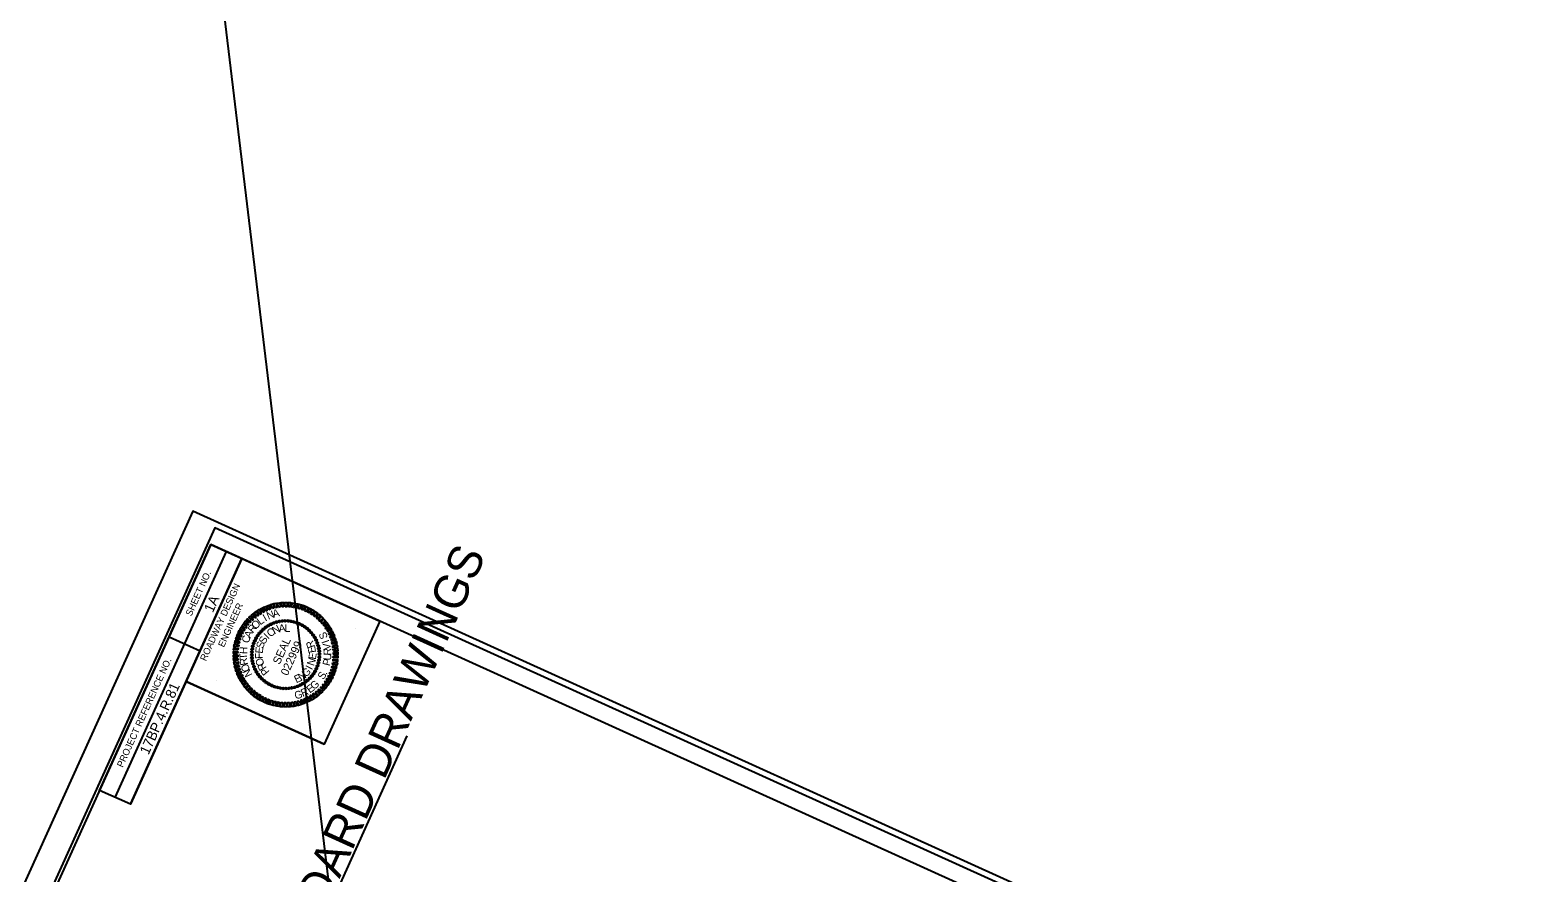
# Model space of a CAD drawing. Extents: x 1744741 to 2014229, y 466994 to 951338.
# Drawn here: x 2007510 to 2010026, y 478827 to 480232 of the extents above; entities that cross this region are included whole.
import ezdxf

# ---------------------------------------------------------------- set-up
doc = ezdxf.new("R2010")
doc.units = 0
for name, color, linetype in [('Old_Level_1', 7, 'Continuous'), ('Prop Guardrail', 7, 'Continuous'), ('Prop Guardrail Anchor Unit CELL', 7, 'Continuous'), ('Sheet Data Field CELL', 7, 'Continuous'), ('Sheet Plan CELL', 7, 'Continuous'), ('Sheet Plot Border Inside CELL', 7, 'Continuous'), ('Sheet Plot Border Outside CELL', 7, 'Continuous'), ('Sheet Sticker Preliminary CELL', 7, 'Continuous')]:
    doc.layers.add(name, color=color, linetype=linetype)

msp = doc.modelspace()

# ---------------------------------------------------------------- linework, layer by layer
at = {"layer": 'Old_Level_1'}
msp.add_line((2007533.4, 477718), (2008139.4, 479055), dxfattribs=at)
at = {"layer": 'Prop Guardrail'}
for p, q in [((2007903.6, 479236.4), (2007903.6, 479236.4)), ((2007907.8, 479239.1), (2007907.8, 479239.1)), ((2007912.1, 479241.4), (2007912.1, 479241.4)), ((2007916.7, 479243.3), (2007916.7, 479243.3)), ((2007921.3, 479244.9), (2007921.3, 479244.9)), ((2007926, 479246), (2007926, 479246)), ((2007931, 479246.7), (2007931, 479246.7)), ((2007935.9, 479247), (2007935.9, 479247)), ((2007940.7, 479246.9), (2007940.7, 479246.9)), ((2007945.7, 479246.2), (2007945.7, 479246.2)), ((2007950.6, 479245.1), (2007950.6, 479245.1)), ((2007955.2, 479243.8), (2007955.2, 479243.8)), ((2007959.8, 479241.9), (2007959.8, 479241.9)), ((2007964.2, 479239.7), (2007964.2, 479239.7)), ((2007968.4, 479237), (2007968.4, 479237)), ((2007885, 479213.8), (2007885, 479213.8)), ((2007887.3, 479218.2), (2007887.3, 479218.2)), ((2007889.9, 479222.4), (2007889.9, 479222.4)), ((2007892.9, 479226.3), (2007892.9, 479226.3)), ((2007896.1, 479230.1), (2007896.1, 479230.1)), ((2007899.8, 479233.3), (2007899.8, 479233.3)), ((2007972.3, 479234.2), (2007972.3, 479234.2)), ((2007976, 479230.9), (2007976, 479230.9)), ((2007979.3, 479227.3), (2007979.3, 479227.3)), ((2007982.5, 479223.4), (2007982.5, 479223.4)), ((2007985.1, 479219.2), (2007985.1, 479219.2)), ((2007987.5, 479214.9), (2007987.5, 479214.9)), ((2007989.4, 479210.4), (2007989.4, 479210.4)), ((2008052.6, 479233.7), (2008052.6, 479233.7)), ((2007880.1, 479194.8), (2007880.1, 479194.8)), ((2007880.1, 479189.9), (2007880.1, 479189.9)), ((2007880.8, 479199.7), (2007880.8, 479199.7)), ((2007881.8, 479204.5), (2007881.8, 479204.5)), ((2007883.2, 479209.2), (2007883.2, 479209.2)), ((2007936.5, 479190.5), (2007936.5, 479190.5)), ((2007991, 479205.7), (2007991, 479205.7)), ((2007992, 479200.9), (2007992, 479200.9)), ((2007992.8, 479196), (2007992.8, 479196)), ((2007992.8, 479186.2), (2007992.8, 479186.2)), ((2007993, 479191.1), (2007993, 479191.1)), ((2007880.3, 479184.9), (2007880.3, 479184.9)), ((2007881.1, 479180), (2007881.1, 479180)), ((2007882.1, 479175.2), (2007882.1, 479175.2)), ((2007883.7, 479170.6), (2007883.7, 479170.6)), ((2007885.6, 479166), (2007885.6, 479166)), ((2007887.9, 479161.8), (2007887.9, 479161.8)), ((2007985.6, 479162.8), (2007985.6, 479162.8)), ((2007987.9, 479167.2), (2007987.9, 479167.2)), ((2007989.7, 479171.8), (2007989.7, 479171.8)), ((2007991.1, 479176.5), (2007991.1, 479176.5)), ((2007992.3, 479181.3), (2007992.3, 479181.3)), ((2007820.5, 479147.2), (2007820.5, 479147.2)), ((2007890.6, 479157.5), (2007890.6, 479157.5)), ((2007893.6, 479153.7), (2007893.6, 479153.7)), ((2007896.9, 479150.1), (2007896.9, 479150.1)), ((2007900.6, 479146.9), (2007900.6, 479146.9)), ((2007904.7, 479143.9), (2007904.7, 479143.9)), ((2007908.7, 479141.3), (2007908.7, 479141.3)), ((2007913.1, 479139.1), (2007913.1, 479139.1)), ((2007917.7, 479137.2), (2007917.7, 479137.2)), ((2007922.5, 479135.8), (2007922.5, 479135.8)), ((2007927.2, 479134.8), (2007927.2, 479134.8)), ((2007946.9, 479135), (2007946.9, 479135)), ((2007951.8, 479136), (2007951.8, 479136)), ((2007956.4, 479137.6), (2007956.4, 479137.6)), ((2007961, 479139.5), (2007961, 479139.5)), ((2007965.3, 479141.9), (2007965.3, 479141.9)), ((2007969.5, 479144.5), (2007969.5, 479144.5)), ((2007973.3, 479147.6), (2007973.3, 479147.6)), ((2007976.8, 479151), (2007976.8, 479151)), ((2007980.2, 479154.6), (2007980.2, 479154.6)), ((2007983, 479158.7), (2007983, 479158.7)), ((2007932.2, 479134.2), (2007932.2, 479134.2)), ((2007937, 479134), (2007937, 479134)), ((2007942.1, 479134.2), (2007942.1, 479134.2))]:
    msp.add_line(p, q, dxfattribs=at)
for points in [[(2007889, 479254.8), (2007884.3, 479260.1), (2007887.3, 479262.5), (2007891.1, 479256.1)], [(2007893.5, 479257.6), (2007889.2, 479263.8), (2007892.4, 479265.6), (2007895.8, 479259.3)], [(2007898.3, 479260.6), (2007894.4, 479266.7), (2007897.7, 479268.6), (2007900.6, 479261.8)], [(2007903.4, 479263.1), (2007899.7, 479269.7), (2007903.3, 479271), (2007905.7, 479264.4)], [(2007908.5, 479265.2), (2007905.6, 479271.8), (2007909.2, 479273.1), (2007910.9, 479266.1)], [(2007913.9, 479267.2), (2007911.3, 479273.9), (2007915, 479275), (2007916.4, 479267.8)], [(2007919.2, 479268.6), (2007916.9, 479275.6), (2007920.9, 479276.1), (2007921.6, 479269)], [(2007924.5, 479269.4), (2007923.1, 479276.6), (2007926.9, 479277.2), (2007927.3, 479270)], [(2007930.3, 479270.1), (2007929.2, 479277.4), (2007932.9, 479277.5), (2007932.7, 479270.5)], [(2007935.6, 479270.3), (2007935.2, 479277.7), (2007938.9, 479277.7), (2007938.3, 479270.3)], [(2007941.2, 479270.1), (2007941.3, 479277.5), (2007944.9, 479277.3), (2007943.9, 479270.1)], [(2007946.9, 479269.7), (2007947.3, 479277.2), (2007951.2, 479276.4), (2007949.5, 479269.3)], [(2007952.4, 479268.7), (2007953.2, 479276), (2007957, 479275.2), (2007954.9, 479268.3)], [(2007957.7, 479267.4), (2007959.3, 479274.8), (2007963, 479273.6), (2007960.4, 479266.8)], [(2007963, 479265.9), (2007965, 479273.1), (2007968.6, 479271.7), (2007965.5, 479265)], [(2007968.2, 479263.8), (2007970.8, 479270.7), (2007974.3, 479269.1), (2007970.7, 479262.7)], [(2007973.3, 479261.5), (2007976.3, 479268.2), (2007979.7, 479266.4), (2007975.7, 479260.2)], [(2007978.1, 479258.9), (2007981.6, 479265.1), (2007984.9, 479263.1), (2007980.3, 479257.2)], [(2007983, 479255.6), (2007986.6, 479261.8), (2007989.7, 479259.5), (2007984.7, 479254)], [(2007866.8, 479229.7), (2007860.4, 479233), (2007862.3, 479236.2), (2007868.3, 479232)], [(2007869.8, 479234.3), (2007863.6, 479238.1), (2007865.6, 479241.3), (2007871.2, 479236.7)], [(2007873.2, 479239.1), (2007866.9, 479243), (2007869.3, 479246.2), (2007874.6, 479241)], [(2007876.7, 479243.4), (2007871, 479247.7), (2007873.2, 479250.5), (2007878.3, 479245.3)], [(2007880.4, 479247.3), (2007875.1, 479252.4), (2007877.7, 479254.8), (2007882.4, 479249.4)], [(2007884.6, 479251.1), (2007879.6, 479256.3), (2007882.4, 479258.8), (2007886.6, 479252.9)], [(2007987.4, 479252.2), (2007991.5, 479258.1), (2007994.5, 479255.9), (2007989.1, 479250.5)], [(2007991.6, 479248.5), (2007996.2, 479254.1), (2007998.9, 479251.4), (2007993.2, 479246.5)], [(2007995.3, 479244.5), (2008000.4, 479249.8), (2008003, 479246.9), (2007997.1, 479242.5)], [(2007999.1, 479240.4), (2008004.2, 479245.2), (2008006.8, 479242.2), (2008000.6, 479238.3)], [(2008002.5, 479235.9), (2008008, 479240.5), (2008010.2, 479237.1), (2008003.6, 479233.6)], [(2007858.7, 479209.2), (2007851.6, 479210.3), (2007852.7, 479213.9), (2007859.6, 479211.7)], [(2007860.3, 479214.4), (2007853.2, 479216.1), (2007854.3, 479219.7), (2007861, 479217)], [(2007862, 479219.8), (2007855.1, 479222.1), (2007856.7, 479225.4), (2007863.1, 479222.3)], [(2007864.3, 479224.7), (2007857.6, 479227.5), (2007859.1, 479230.9), (2007865.4, 479227.2)], [(2008005.2, 479231.1), (2008011.3, 479235.2), (2008013.3, 479231.9), (2008006.7, 479228.9)], [(2008007.8, 479226.4), (2008014.3, 479229.9), (2008016, 479226.5), (2008009.2, 479224)], [(2008010.3, 479221), (2008016.8, 479224.4), (2008018.1, 479220.8), (2008011.2, 479218.6)], [(2008012.5, 479216), (2008018.9, 479218.6), (2008020.2, 479215), (2008013, 479213.4)], [(2008013.7, 479210.6), (2008020.7, 479212.9), (2008021.7, 479209.1), (2008014.3, 479208)], [(2007856.5, 479192.4), (2007849.3, 479192.3), (2007849.4, 479195.9), (2007856.8, 479195.2)], [(2007856.7, 479186.9), (2007849.5, 479186.1), (2007849.5, 479189.9), (2007856.7, 479189.6)], [(2007856.9, 479198.2), (2007849.7, 479198.5), (2007850.3, 479202), (2007857.3, 479200.6)], [(2007857.7, 479203.7), (2007850.3, 479204.3), (2007851.1, 479208.2), (2007858.3, 479206.1)], [(2008015.2, 479205.2), (2008022.1, 479206.8), (2008023, 479203.2), (2008015.4, 479202.4)], [(2008015.9, 479199.6), (2008023, 479201.1), (2008023.4, 479197), (2008016.3, 479197.1)], [(2008016.6, 479188.5), (2008023.8, 479188.6), (2008023.7, 479185.1), (2008016.1, 479185.8)], [(2008016.4, 479194.1), (2008023.6, 479194.8), (2008023.6, 479191), (2008016.4, 479191.3)], [(2007857.2, 479181.3), (2007849.9, 479180), (2007849.7, 479183.9), (2007856.9, 479183.9)], [(2007857.9, 479175.7), (2007851, 479174.2), (2007850.1, 479177.8), (2007857.7, 479178.5)], [(2007859.2, 479170.4), (2007852.2, 479168.2), (2007851.4, 479171.9), (2007858.6, 479173)], [(2007860.6, 479165), (2007854, 479162.4), (2007852.7, 479166), (2007860.1, 479167.6)], [(2007862.8, 479159.9), (2007856.3, 479156.5), (2007855, 479160.1), (2007861.9, 479162.3)], [(2008010.9, 479161.2), (2008018, 479158.9), (2008016.4, 479155.5), (2008009.8, 479158.8)], [(2008012.8, 479166.5), (2008019.7, 479164.9), (2008018.8, 479161.2), (2008011.9, 479164)], [(2008014.2, 479171.8), (2008021.5, 479170.6), (2008020.4, 479167), (2008013.5, 479169.2)], [(2008015.2, 479177.3), (2008022.8, 479176.6), (2008021.8, 479172.8), (2008014.8, 479174.9)], [(2008016, 479182.9), (2008023.3, 479182.5), (2008022.8, 479178.9), (2008015.8, 479180.3)], [(2007865.1, 479154.7), (2007858.8, 479151), (2007857.1, 479154.5), (2007863.9, 479156.9)], [(2007867.7, 479149.9), (2007861.8, 479145.8), (2007859.6, 479149.1), (2007866.4, 479152)], [(2007870.6, 479145), (2007864.9, 479140.6), (2007862.9, 479143.8), (2007869.3, 479147.5)], [(2007873.8, 479140.6), (2007868.7, 479135.9), (2007866.3, 479138.7), (2007872.5, 479142.7)], [(2007877.6, 479136.5), (2007872.5, 479131.2), (2007870.1, 479134), (2007875.8, 479138.6)], [(2007996.4, 479137.5), (2008002.1, 479133.2), (2007999.7, 479130.5), (2007994.6, 479135.7)], [(2007999.9, 479141.9), (2008006, 479138), (2008003.8, 479134.8), (2007998.3, 479140)], [(2008003.3, 479146.6), (2008009.5, 479142.8), (2008007.5, 479139.6), (2008001.7, 479144.4)], [(2008006.1, 479151.3), (2008012.7, 479147.9), (2008010.6, 479144.8), (2008004.8, 479148.9)], [(2008008.6, 479156.3), (2008015.5, 479153.4), (2008014, 479150.1), (2008007.5, 479153.8)], [(2007881.5, 479132.4), (2007876.7, 479126.9), (2007874.2, 479129.5), (2007879.7, 479134.5)], [(2007885.7, 479128.8), (2007881.6, 479122.9), (2007878.4, 479125.2), (2007883.8, 479130.5)], [(2007890.1, 479125.3), (2007886.4, 479119.2), (2007883.2, 479121.5), (2007888.2, 479127)], [(2007894.9, 479122.2), (2007891.5, 479115.8), (2007888.2, 479117.8), (2007892.6, 479123.8)], [(2007899.6, 479119.5), (2007896.6, 479112.9), (2007893.2, 479114.6), (2007897.2, 479120.8)], [(2007904.7, 479117.2), (2007902.3, 479110.3), (2007898.8, 479111.8), (2007902.2, 479118.3)], [(2007909.9, 479115.1), (2007907.9, 479108), (2007904.4, 479109.3), (2007907.4, 479116)], [(2007915.2, 479113.6), (2007913.8, 479106.2), (2007910.1, 479107.3), (2007912.5, 479114.2)], [(2007920.5, 479112.4), (2007919.7, 479105), (2007915.9, 479105.8), (2007918.2, 479112.6)], [(2007926, 479111.4), (2007925.6, 479103.8), (2007922, 479104.6), (2007923.7, 479111.6)], [(2007931.7, 479110.9), (2007931.8, 479103.4), (2007928, 479103.7), (2007929.2, 479110.8)], [(2007937.3, 479110.7), (2007937.9, 479103.3), (2007934, 479103.3), (2007934.6, 479110.7)], [(2007942.8, 479110.8), (2007943.9, 479103.5), (2007940, 479103.5), (2007940.2, 479110.5)], [(2007948.4, 479111.6), (2007950, 479104.3), (2007946.1, 479103.8), (2007945.8, 479110.9)], [(2007953.9, 479112.3), (2007956, 479105.5), (2007952.2, 479104.8), (2007951.3, 479112)], [(2007959.2, 479113.7), (2007961.8, 479107), (2007958.2, 479105.9), (2007956.5, 479113.2)], [(2007964.6, 479115.8), (2007967.5, 479109.1), (2007963.9, 479107.8), (2007962.2, 479114.9)], [(2007969.7, 479117.9), (2007973.2, 479111.4), (2007969.6, 479110), (2007967.4, 479116.6)], [(2007974.6, 479120.5), (2007978.7, 479114.2), (2007975.2, 479112.4), (2007972.3, 479119.2)], [(2007979.6, 479123.3), (2007984, 479117.1), (2007980.7, 479115.4), (2007977.3, 479121.6)], [(2007984.1, 479126.2), (2007988.9, 479120.8), (2007985.6, 479118.5), (2007982, 479124.8)], [(2007988.5, 479129.9), (2007993.5, 479124.6), (2007990.7, 479122.1), (2007986.5, 479128.1)], [(2007992.5, 479133.7), (2007998, 479128.5), (2007995.4, 479126.1), (2007990.8, 479131.6)]]:
    msp.add_lwpolyline(points, close=True, dxfattribs=at)
for centre, major_axis in [((2007903.6, 479236.3), (-0.94, 1.32)), ((2007907.8, 479239), (-0.83, 1.39)), ((2007912.1, 479241.3), (-0.7, 1.46)), ((2007916.6, 479243.3), (-0.57, 1.52)), ((2007921.3, 479244.8), (-0.44, 1.56)), ((2007926.1, 479245.9), (-0.3, 1.59)), ((2007931, 479246.6), (-0.16, 1.61)), ((2007935.9, 479246.9), (-0.02, 1.62)), ((2007940.8, 479246.7), (0.12, 1.62)), ((2007945.7, 479246.1), (0.26, 1.6)), ((2007950.5, 479245.1), (0.4, 1.57)), ((2007955.2, 479243.7), (0.54, 1.53)), ((2007959.8, 479241.9), (0.67, 1.48)), ((2007964.2, 479239.6), (0.79, 1.41)), ((2007968.4, 479237), (0.91, 1.34)), ((2007972.3, 479234.1), (1.03, 1.25)), ((2007883.3, 479209.2), (-1.53, 0.54)), ((2007885.1, 479213.7), (-1.48, 0.67)), ((2007887.3, 479218.1), (-1.41, 0.79)), ((2007889.9, 479222.3), (-1.34, 0.91)), ((2007892.9, 479226.3), (-1.25, 1.03)), ((2007896.2, 479229.9), (-1.16, 1.13)), ((2007899.8, 479233.3), (-1.05, 1.23)), ((2007976, 479230.8), (1.13, 1.16)), ((2007979.3, 479227.2), (1.23, 1.05)), ((2007982.4, 479223.3), (1.32, 0.94)), ((2007985.1, 479219.2), (1.39, 0.83)), ((2007987.4, 479214.9), (1.46, 0.7)), ((2007989.3, 479210.3), (1.52, 0.57)), ((2007880.1, 479189.8), (-1.62, -0.02)), ((2007880.2, 479194.8), (-1.62, 0.12)), ((2007880.3, 479184.9), (-1.61, -0.16)), ((2007880.8, 479199.7), (-1.6, 0.26)), ((2007881.8, 479204.5), (-1.57, 0.4)), ((2007990.8, 479205.6), (1.56, 0.44)), ((2007992, 479200.9), (1.59, 0.3)), ((2007992.7, 479196), (1.61, 0.16)), ((2007992.8, 479186.1), (1.62, -0.12)), ((2007992.9, 479191.1), (1.62, 0.02)), ((2007881, 479180.1), (-1.59, -0.3)), ((2007882.2, 479175.3), (-1.56, -0.44)), ((2007883.7, 479170.6), (-1.52, -0.57)), ((2007885.6, 479166.1), (-1.46, -0.7)), ((2007887.9, 479161.7), (-1.39, -0.83)), ((2007983.1, 479158.6), (1.34, -0.91)), ((2007985.7, 479162.8), (1.41, -0.79)), ((2007987.9, 479167.2), (1.48, -0.67)), ((2007989.7, 479171.7), (1.53, -0.54)), ((2007991.2, 479176.4), (1.57, -0.4)), ((2007992.2, 479181.3), (1.6, -0.26)), ((2007890.6, 479157.6), (-1.32, -0.94)), ((2007893.7, 479153.7), (-1.23, -1.05)), ((2007897, 479150.1), (-1.13, -1.16)), ((2007900.7, 479146.8), (-1.03, -1.25)), ((2007904.6, 479143.9), (-0.91, -1.34)), ((2007908.8, 479141.3), (-0.79, -1.41)), ((2007913.2, 479139.1), (-0.67, -1.48)), ((2007917.8, 479137.2), (-0.54, -1.53)), ((2007922.5, 479135.8), (-0.4, -1.57)), ((2007927.3, 479134.8), (-0.26, -1.6)), ((2007932.2, 479134.2), (-0.12, -1.62)), ((2007937.1, 479134), (0.02, -1.62)), ((2007942, 479134.3), (0.16, -1.61)), ((2007946.9, 479135), (0.3, -1.59)), ((2007951.7, 479136.1), (0.44, -1.56)), ((2007956.4, 479137.6), (0.57, -1.52)), ((2007960.9, 479139.6), (0.7, -1.46)), ((2007965.2, 479141.9), (0.83, -1.39)), ((2007969.4, 479144.6), (0.94, -1.32)), ((2007973.2, 479147.6), (1.05, -1.23)), ((2007976.8, 479151), (1.16, -1.13)), ((2007980.1, 479154.6), (1.25, -1.03))]:
    msp.add_ellipse(centre, major_axis=major_axis, ratio=0.999708, dxfattribs=at)
at = {"layer": 'Prop Guardrail Anchor Unit CELL'}
msp.add_line((2008573.3, 474121.5), (2007740.2, 481039.5), dxfattribs=at)
at = {"layer": 'Sheet Plan CELL'}
for p, q in [((2007651.9, 478952.5), (2007837.8, 479362.4)), ((2007677.5, 478940.9), (2007863.4, 479350.8)), ((2007677.5, 478940.9), (2007863.4, 479350.8)), ((2007742.5, 479220.3), (2007793.7, 479197.1)), ((2007770.5, 479145.9), (2008000.9, 479041.4))]:
    msp.add_line(p, q, dxfattribs=at)
for points in [[(2007812, 479374.1), (2006418.7, 476300.1), (2008570.5, 475324.8), (2009963.8, 478398.8)], [(2007626.2, 478964.1), (2007812, 479374.1), (2007863.4, 479350.8), (2007677.5, 478940.9)], [(2007770.5, 479145.9), (2007863.4, 479350.8), (2008093.9, 479246.3), (2008001, 479041.4)]]:
    msp.add_lwpolyline(points, close=True, dxfattribs=at)
at = {"layer": 'Sheet Plot Border Inside CELL'}
msp.add_lwpolyline([(2008433, 475007.9), (2009980.5, 478422.1), (2007818.5, 479402), (2006271, 475987.9)], close=True, dxfattribs=at)
at = {"layer": 'Sheet Plot Border Outside CELL'}
msp.add_lwpolyline([(2008462, 474962.7), (2010025.7, 478412.7), (2007781.7, 479429.8), (2006218, 475979.8)], close=True, dxfattribs=at)

# ---------------------------------------------------------------- texts
at = {"layer": 'Prop Guardrail'}
for s, height, rotation, p in [('N', 12.7, 22.436, (2007907.9, 479248.5)), ('A', 12.7, 15.2343, (2007916.6, 479252)), ('R', 12.7, 51.2382, (2007881.9, 479225.6)), ('O', 12.7, 44.0383, (2007886.5, 479231.8)), ('L', 12.7, 36.838, (2007894.3, 479239.3)), ('I', 12.7, 29.6373, (2007902.8, 479245.5)), ('N', 12.7, 27.0937, (2007917.9, 479224.1)), ('A', 12.7, 8.3774, (2007925.9, 479227.7)), ('L', 12.7, 359.018, (2007934.7, 479228.6)), ('C', 12.7, 72.837, (2007874.8, 479208.7)), ('A', 12.7, 65.6374, (2007877.8, 479217.1)), ('S', 12.7, 73.8727, (2007899.1, 479199.8)), ('S', 12.7, 64.5175, (2007902.3, 479207.2)), ('I', 12.7, 45.8067, (2007907.5, 479215.5)), ('O', 12.7, 36.4506, (2007910.8, 479219)), ('SEAL', 13.5, 65.6171, (2007926.6, 479173.1)), ('022999', 13.5, 65.6171, (2007939.8, 479154.4)), ('R', 12.7, 109.0985, (2007985.7, 479203.8)), ('S', 12.7, 109.6866, (2008007.2, 479218.9)), ('I', 12.7, 109.6866, (2008009.6, 479212.1)), ('T', 12.7, 94.4369, (2007872.7, 479182.9)), ('H', 12.7, 87.2366, (2007872.3, 479191.2)), ('R', 12.7, 101.6376, (2007874.1, 479174)), ('F', 12.7, 92.5841, (2007898.5, 479183.7)), ('E', 12.7, 83.2282, (2007898.2, 479191.8)), ('N', 12.7, 71.6735, (2007983.6, 479170.9)), ('E', 12.7, 99.7412, (2007987.4, 479194.4)), ('E', 12.7, 81.0289, (2007986.8, 479181.7)), ('V', 12.7, 96.4626, (2008012.1, 479198.9)), ('U', 12.7, 83.2387, (2008011.9, 479180.3)), ('R', 12.7, 89.8506, (2008012.6, 479189.2)), ('O', 12.7, 108.8389, (2007877.5, 479164.1)), ('N', 12.7, 116.0406, (2007881.4, 479156.8)), ('O', 12.7, 111.2984, (2007901.7, 479174.3)), ('R', 12.7, 120.6568, (2007905.2, 479168.5)), ('P', 12.7, 130.016, (2007910.3, 479162.3)), ('N', 12.7, 34.2511, (2007962.4, 479146.4)), ('G', 12.7, 43.6074, (2007970.5, 479152.2)), ('I', 12.7, 62.3183, (2007980.3, 479164.1)), ('S', 12.7, 56.7907, (2007999.4, 479147.6)), ('P', 12.7, 76.6267, (2008010.1, 479170.9)), ('.', 12.7, 63.4027, (2008004.7, 479156.5)), ('E', 12.7, 24.894, (2007954.3, 479142.7)), ('R', 12.7, 23.7307, (2007965.1, 479119.9)), ('E', 12.7, 36.9547, (2007977, 479125.6)), ('G', 12.7, 43.5667, (2007984.6, 479131.2)), ('G', 12.7, 12.5581, (2007952.7, 479116.1))]:
    msp.add_text(s, height=height, rotation=rotation, dxfattribs=at).set_placement(p)
at = {"layer": 'Sheet Data Field CELL'}
for s, height, p in [('1A ', 16.87, (2007815, 479259.4)), ('17BP.4.R.81', 16.875, (2007707.7, 479022.4))]:
    msp.add_text(s, height=height, rotation=65.6171, dxfattribs=at).set_placement(p)
at = {"layer": 'Sheet Plan CELL'}
for s, p in [('SHEET NO.', (2007779.3, 479253.8)), ('ROADWAY DESIGN', (2007803.5, 479178.9)), ('ENGINEER', (2007833.5, 479201.9)), ('PROJECT REFERENCE NO.', (2007664.7, 479001.5))]:
    msp.add_text(s, height=11.25, rotation=65.6171, dxfattribs=at).set_placement(p)
at = {"layer": 'Sheet Sticker Preliminary CELL'}
msp.add_text('2018 ROADWAY ENGLISH STANDARD DRAWINGS', height=56.25, rotation=65.6171, dxfattribs=at).set_placement((2007529.5, 477719.6))

doc.saveas('drawing.dxf')
